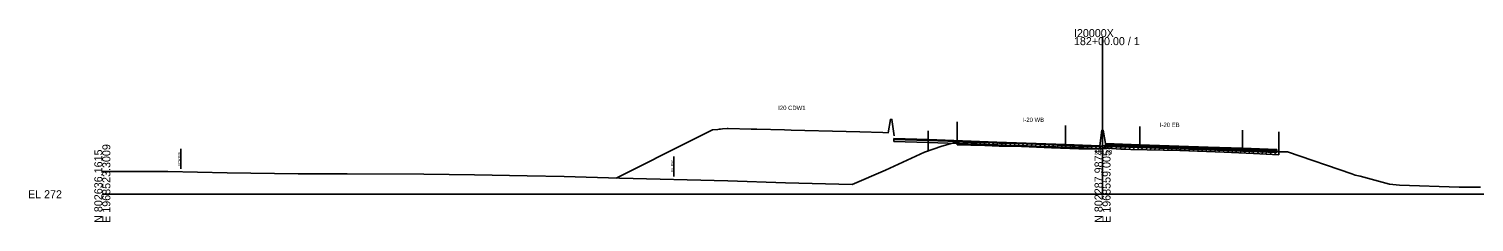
# Model space of a CAD drawing. Extents: x -4026 to 9638, y -10 to 19609.
# Drawn here: x 4974 to 5480, y 3490 to 3558 of the extents above; entities that cross this region are included whole.
import ezdxf

# ---------------------------------------------------------------- set-up
doc = ezdxf.new("R2010")
doc.units = 0
for name, color, linetype in [('Default', 7, 'Continuous'), ('RD_EX_Road', 7, 'Continuous'), ('RD_GPK_XS_Cell', 7, 'Continuous'), ('RD_PD_ALT1_TrvlWay', 7, 'Continuous'), ('RD_TX_Misc1', 7, 'Continuous'), ('RD_XS_Base', 7, 'Continuous'), ('RD_XS_ExGround', 7, 'Continuous'), ('RD_XS_ExPaveRet', 7, 'Continuous'), ('RD_XS_ExRW', 7, 'Continuous'), ('RD_XS_MedBWall', 7, 'Continuous'), ('RD_XS_NewRW', 7, 'Continuous'), ('RD_XS_Pave', 7, 'Continuous'), ('RD_XS_PaveOvlay', 7, 'Continuous'), ('RD_XS_TX_Elev_EX', 7, 'Continuous')]:
    doc.layers.add(name, color=color, linetype=linetype)

msp = doc.modelspace()

# ---------------------------------------------------------------- linework, layer by layer
at = {"layer": 'RD_EX_Road'}
for p, q in [((5299.07, 3525.27), (5299.07, 3518.27)), ((5411.74, 3521.78), (5411.74, 3514.78))]:
    msp.add_line(p, q, dxfattribs=at)
at = {"layer": 'RD_GPK_XS_Cell'}
for p, q in [((5350, 3500), (5350, 3554.82)), ((5000, 3500), (5350, 3500)), ((5350, 3500), (5700, 3500))]:
    msp.add_line(p, q, dxfattribs=at)
at = {"layer": 'RD_PD_ALT1_TrvlWay'}
for p, q in [((5289, 3522.11), (5289, 3515.11)), ((5337, 3524.01), (5337, 3517.01)), ((5363, 3523.58), (5363, 3516.58)), ((5399, 3522.41), (5399, 3515.41))]:
    msp.add_line(p, q, dxfattribs=at)
at = {"layer": 'RD_XS_Base'}
for points in [[(5277, 3519.11), (5277, 3518.44)], [(5289, 3518.7), (5277, 3519.11)], [(5277, 3518.44), (5289, 3518.03)], [(5337, 3517.07), (5313, 3517.89), (5289, 3518.7)], [(5289, 3518.7), (5289, 3518.03)], [(5289, 3518.7), (5289, 3518.7), (5289, 3518.03), (5289, 3518.03)], [(5289, 3518.03), (5313, 3517.22), (5337, 3516.4)], [(5337, 3516.4), (5337, 3517.07)], [(5349, 3516.6), (5337, 3517.07)], [(5337, 3516.4), (5349, 3515.93)], [(5349, 3515.93), (5349, 3516.6)], [(5351, 3516.69), (5351, 3517.36)], [(5351, 3517.36), (5363, 3516.94)], [(5363, 3516.27), (5351, 3516.69)], [(5363, 3516.27), (5363, 3516.94)], [(5363, 3516.94), (5387, 3516.13), (5399, 3515.71)], [(5399, 3515.04), (5387, 3515.46), (5363, 3516.27)], [(5399, 3515.71), (5399, 3515.71), (5399, 3515.04), (5399, 3515.04)], [(5399, 3515.04), (5399, 3515.71)], [(5399, 3515.71), (5411, 3515.23)], [(5411, 3514.56), (5399, 3515.04)], [(5411, 3515.23), (5411, 3514.56)]]:
    msp.add_lwpolyline(points, dxfattribs=at)
at = {"layer": 'RD_XS_ExGround'}
msp.add_lwpolyline([(5000, 3507.92), (5002.61, 3507.88), (5022.87, 3507.97), (5043.72, 3507.52), (5068.55, 3507.16), (5085.69, 3507.14), (5112.48, 3506.95), (5130.22, 3506.81), (5148.69, 3506.38), (5161.58, 3506.13), (5181, 3505.6), (5218.86, 3504.69), (5239.08, 3503.98), (5262.39, 3503.37), (5274.01, 3508.44), (5287.66, 3514.65), (5293.72, 3516.73), (5299.07, 3518.27), (5303.86, 3518.1), (5308.8, 3518.02), (5313.84, 3517.82), (5321.64, 3517.7), (5332.14, 3517.21), (5341.74, 3516.81), (5342.73, 3516.79), (5348.75, 3516.71), (5350, 3516.89), (5350.39, 3516.94), (5351.52, 3517.13), (5356.45, 3516.77), (5358.08, 3516.69), (5359.93, 3516.64), (5377.06, 3516.28), (5392.55, 3515.66), (5402.82, 3515.27), (5411.74, 3514.78), (5414.68, 3514.84), (5437.25, 3507.13), (5438.45, 3506.7), (5440.14, 3506.28), (5450.38, 3503.49), (5453.89, 3503.21), (5474.75, 3502.42), (5478.29, 3502.43), (5482.31, 3502.41)], dxfattribs=at)
at = {"layer": 'RD_XS_ExPaveRet'}
for p, q in [((5299.07, 3517.27), (5299.07, 3518.27)), ((5299.07, 3517.27), (5300.04, 3518.24)), ((5299.07, 3517.27), (5303.86, 3517.1)), ((5300.57, 3517.22), (5301.54, 3518.19)), ((5302.07, 3517.17), (5303.04, 3518.13)), ((5303.57, 3517.11), (5304.55, 3518.09)), ((5303.86, 3517.1), (5308.8, 3517.02)), ((5305.07, 3517.08), (5306.05, 3518.07)), ((5306.57, 3517.06), (5307.55, 3518.04)), ((5308.07, 3517.03), (5309.05, 3518.01)), ((5308.8, 3517.02), (5313.84, 3516.82)), ((5309.57, 3516.99), (5310.53, 3517.95)), ((5311.07, 3516.93), (5312.03, 3517.89)), ((5312.57, 3516.87), (5313.53, 3517.83)), ((5313.84, 3516.82), (5321.64, 3516.7)), ((5314.07, 3516.82), (5315.06, 3517.8)), ((5315.57, 3516.79), (5316.56, 3517.78)), ((5317.07, 3516.77), (5318.06, 3517.76)), ((5318.57, 3516.75), (5319.56, 3517.73)), ((5320.07, 3516.73), (5321.06, 3517.71)), ((5321.57, 3516.7), (5322.53, 3517.66)), ((5321.64, 3516.7), (5332.14, 3516.21)), ((5323.07, 3516.64), (5324.03, 3517.59)), ((5324.57, 3516.57), (5325.53, 3517.52)), ((5326.07, 3516.5), (5327.03, 3517.45)), ((5327.57, 3516.43), (5328.53, 3517.38)), ((5329.07, 3516.36), (5330.03, 3517.31)), ((5330.57, 3516.29), (5331.53, 3517.24)), ((5332.07, 3516.22), (5333.03, 3517.18)), ((5332.14, 3516.21), (5341.74, 3515.81)), ((5333.57, 3516.15), (5334.53, 3517.11)), ((5335.07, 3516.09), (5336.03, 3517.05)), ((5336.57, 3516.03), (5337.53, 3516.99)), ((5338.07, 3515.97), (5339.03, 3516.93)), ((5339.57, 3515.9), (5340.53, 3516.86)), ((5341.07, 3515.84), (5342.04, 3516.81)), ((5341.74, 3515.81), (5342.73, 3515.79)), ((5342.57, 3515.8), (5343.56, 3516.78)), ((5342.73, 3515.79), (5348.75, 3515.71)), ((5344.07, 3515.77), (5345.06, 3516.76)), ((5345.57, 3515.76), (5346.56, 3516.74)), ((5347.07, 3515.74), (5348.06, 3516.72)), ((5348.57, 3515.72), (5349.7, 3516.85)), ((5348.75, 3515.71), (5350, 3515.89)), ((5350, 3515.89), (5350.39, 3515.94)), ((5350.07, 3515.9), (5351.26, 3517.09)), ((5350.39, 3515.94), (5351.52, 3516.13)), ((5351.52, 3516.13), (5356.45, 3515.77)), ((5351.57, 3516.13), (5352.5, 3517.06)), ((5353.07, 3516.02), (5354, 3516.95)), ((5354.57, 3515.91), (5355.5, 3516.84)), ((5356.07, 3515.8), (5357.01, 3516.74)), ((5356.45, 3515.77), (5358.08, 3515.69)), ((5357.57, 3515.71), (5358.53, 3516.68)), ((5358.08, 3515.69), (5359.93, 3515.64)), ((5359.07, 3515.66), (5360.05, 3516.64)), ((5359.93, 3515.64), (5377.06, 3515.28)), ((5360.57, 3515.63), (5361.55, 3516.61)), ((5362.07, 3515.59), (5363.05, 3516.57)), ((5363.57, 3515.56), (5364.55, 3516.54)), ((5365.07, 3515.53), (5366.05, 3516.51)), ((5366.57, 3515.5), (5367.55, 3516.48)), ((5368.07, 3515.47), (5369.05, 3516.45)), ((5369.57, 3515.44), (5370.55, 3516.42)), ((5371.07, 3515.41), (5372.05, 3516.39)), ((5372.57, 3515.38), (5373.55, 3516.36)), ((5374.07, 3515.34), (5375.05, 3516.32)), ((5375.57, 3515.31), (5376.55, 3516.29)), ((5377.06, 3515.28), (5392.55, 3514.66)), ((5377.07, 3515.28), (5378.03, 3516.24)), ((5378.57, 3515.22), (5379.53, 3516.18)), ((5380.07, 3515.16), (5381.03, 3516.12)), ((5381.57, 3515.1), (5382.53, 3516.06)), ((5383.07, 3515.04), (5384.03, 3516)), ((5384.57, 3514.98), (5385.53, 3515.94)), ((5386.07, 3514.92), (5387.03, 3515.88)), ((5387.57, 3514.86), (5388.53, 3515.82)), ((5389.07, 3514.8), (5390.03, 3515.76)), ((5390.57, 3514.74), (5391.53, 3515.7)), ((5392.07, 3514.68), (5393.03, 3515.64)), ((5393.57, 3514.62), (5394.53, 3515.58)), ((5395.07, 3514.56), (5396.03, 3515.53)), ((5396.57, 3514.51), (5397.53, 3515.47)), ((5398.07, 3514.45), (5399.03, 3515.41)), ((5399.57, 3514.39), (5400.53, 3515.35)), ((5401.07, 3514.33), (5402.03, 3515.3)), ((5402.57, 3514.28), (5403.52, 3515.23)), ((5404.07, 3514.2), (5405.02, 3515.15)), ((5405.57, 3514.12), (5406.52, 3515.07)), ((5407.07, 3514.04), (5408.02, 3514.99)), ((5408.57, 3513.96), (5409.52, 3514.9)), ((5410.07, 3513.87), (5411.02, 3514.82)), ((5411.74, 3514.78), (5411.74, 3513.78)), ((5392.55, 3514.66), (5402.82, 3514.27)), ((5402.82, 3514.27), (5411.74, 3513.78))]:
    msp.add_line(p, q, dxfattribs=at)
at = {"layer": 'RD_XS_ExRW'}
msp.add_line((5200, 3506.14), (5200, 3513.14), dxfattribs=at)
at = {"layer": 'RD_XS_MedBWall'}
for points in [[(5349, 3516.93), (5349.75, 3522.35), (5350.25, 3522.35), (5351, 3517.68)], [(5349, 3515.93), (5349, 3516.93)], [(5351, 3515.93), (5349, 3515.93)], [(5351, 3517.68), (5351, 3515.93)]]:
    msp.add_lwpolyline(points, dxfattribs=at)
at = {"layer": 'RD_XS_NewRW'}
msp.add_line((5027.47, 3508.87), (5027.47, 3515.87), dxfattribs=at)
at = {"layer": 'RD_XS_Pave'}
for points in [[(5179.8, 3505.62), (5206.95, 3519.19), (5213.54, 3522.49), (5215.36, 3522.64), (5215.81, 3522.67), (5216.31, 3522.71), (5217.04, 3522.77), (5218.64, 3522.9), (5219.04, 3522.93), (5227.07, 3522.74), (5229.04, 3522.69), (5238.67, 3522.46), (5241.04, 3522.4), (5260.32, 3521.94), (5265.04, 3521.83), (5273.07, 3521.51), (5275.04, 3521.43), (5275.79, 3526.1), (5276.29, 3526.1), (5277.04, 3520.43)], [(5277, 3519.28), (5289, 3518.87)], [(5277, 3519.11), (5277, 3519.28)], [(5289, 3518.7), (5277, 3519.11)], [(5289, 3518.87), (5289, 3518.87), (5289, 3518.7), (5289, 3518.7)], [(5289, 3518.7), (5289, 3518.87)], [(5289, 3518.87), (5313, 3518.06), (5337, 3517.24)], [(5337, 3517.07), (5313, 3517.89), (5289, 3518.7)], [(5337, 3517.24), (5349, 3516.77)], [(5337, 3517.07), (5337, 3517.24)], [(5349, 3516.6), (5337, 3517.07)], [(5349, 3516.77), (5349, 3516.6)], [(5363, 3517.11), (5351, 3517.53)], [(5351, 3517.53), (5351, 3517.36)], [(5351, 3517.36), (5363, 3516.94)], [(5399, 3515.88), (5387, 3516.29), (5363, 3517.11)], [(5363, 3517.11), (5363, 3516.94)], [(5363, 3516.94), (5387, 3516.13), (5399, 3515.71)], [(5399, 3515.88), (5399, 3515.88), (5399, 3515.71), (5399, 3515.71)], [(5399, 3515.71), (5399, 3515.88)], [(5399, 3515.88), (5411, 3515.4)], [(5411, 3515.23), (5399, 3515.71)], [(5411, 3515.4), (5411, 3515.23)]]:
    msp.add_lwpolyline(points, dxfattribs=at)
at = {"layer": 'RD_XS_PaveOvlay'}
for points in [[(5277, 3519.45), (5289, 3519.04)], [(5277, 3519.28), (5277, 3519.45)], [(5289, 3518.87), (5277, 3519.28)], [(5289, 3519.04), (5313, 3518.22), (5337, 3517.41)], [(5289, 3518.87), (5289, 3519.04)], [(5289, 3519.04), (5289, 3519.04), (5289, 3518.87), (5289, 3518.87)], [(5337, 3517.24), (5313, 3518.06), (5289, 3518.87)], [(5337, 3517.41), (5337, 3517.24)], [(5337, 3517.41), (5349, 3516.93)], [(5349, 3516.77), (5337, 3517.24)], [(5349, 3516.93), (5349, 3516.77)], [(5363, 3517.28), (5351, 3517.68)], [(5351, 3517.68), (5351, 3517.53)], [(5351, 3517.53), (5363, 3517.11)], [(5399, 3516.05), (5387, 3516.46), (5363, 3517.28)], [(5363, 3517.28), (5363, 3517.11)], [(5363, 3517.11), (5387, 3516.29), (5399, 3515.88)], [(5399, 3515.88), (5399, 3516.05)], [(5399, 3516.05), (5411, 3515.57)], [(5399, 3516.05), (5399, 3516.05), (5399, 3515.88), (5399, 3515.88)], [(5411, 3515.4), (5399, 3515.88)], [(5411, 3515.57), (5411, 3515.4)]]:
    msp.add_lwpolyline(points, dxfattribs=at)

# ---------------------------------------------------------------- texts
at = {"layer": 'Default'}
msp.add_text('-', height=0.0001, dxfattribs=at).set_placement((5000, 3500))
at = {"layer": 'RD_GPK_XS_Cell'}
for s, p in [('I20000X', (5340, 3554.82)), ('182+00.00 / 1', (5340, 3552.02)), ('EL 272', (4974, 3498.6))]:
    msp.add_text(s, height=2.8, dxfattribs=at).set_placement(p)
for s, p in [('N 802636.1615', (5000, 3490)), ('E 1968523.3009', (5002.8, 3490)), ('N 802287.9874', (5350, 3490)), ('E 1968559.0055', (5352.8, 3490))]:
    msp.add_text(s, height=2.8, rotation=90, dxfattribs=at).set_placement(p)
at = {"layer": 'RD_TX_Misc1'}
for s, p in [('I20 CDW1', (5236.52, 3529.39)), ('I-20 WB', (5322.06, 3525.22)), ('I-20 EB', (5370.06, 3523.46))]:
    msp.add_text(s, height=1.5, dxfattribs=at).set_placement(p)
at = {"layer": 'RD_XS_ExRW'}
msp.add_text('EX. R/W ', height=0.75, rotation=90, dxfattribs=at).set_placement((5199.75, 3507.83))
at = {"layer": 'RD_XS_NewRW'}
msp.add_text('NEW R/W ', height=0.75, rotation=90, dxfattribs=at).set_placement((5027.22, 3510.01))
at = {"layer": 'RD_XS_TX_Elev_EX'}
msp.add_text('288.89', height=1.5, dxfattribs=at).set_placement((5347.1, 3513.89))

doc.saveas('drawing.dxf')
